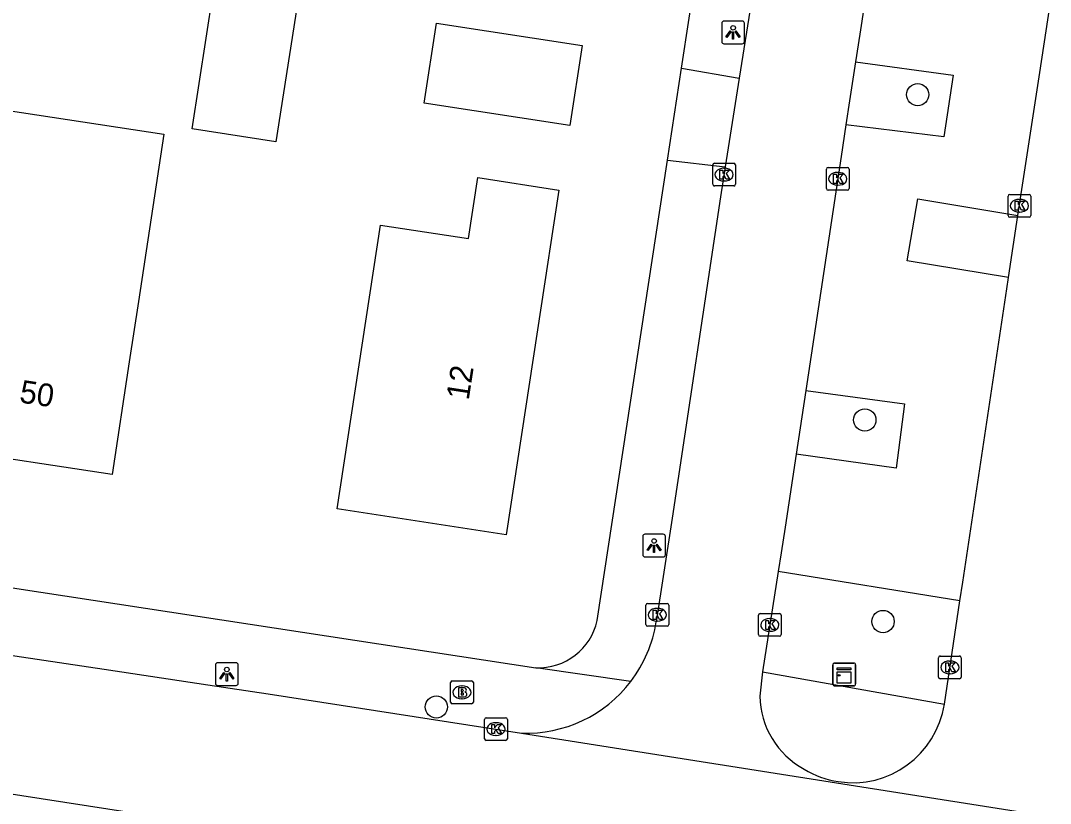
# Model space of a CAD drawing. Extents: x 161486 to 162249, y 379484 to 380829.
# Drawn here: x 161700.97 to 161746.18, y 380443.95 to 380478.3 of the extents above; entities that cross this region are included whole.
import ezdxf

# ---------------------------------------------------------------- set-up
doc = ezdxf.new("R2010")
doc.units = 0
for name, color, linetype in [('IMGEO_Boom', 7, 'Continuous'), ('IMGEO_Brandkraan', 7, 'Continuous'), ('IMGEO_Groenvoorziening', 7, 'Continuous'), ('IMGEO_Kast', 7, 'Continuous'), ('IMGEO_Kolk', 7, 'Continuous'), ('IMGEO_Lichtpunt', 7, 'Continuous'), ('IMGEO_Pand', 7, 'Continuous'), ('IMGEO_Pand_nummerreeks', 7, 'Continuous'), ('IMGEO_Rijbaan_lokaal_open', 7, 'Continuous'), ('IMGEO_Voetpad_open', 7, 'Continuous')]:
    doc.layers.add(name, color=color, linetype=linetype)

msp = doc.modelspace()

# ---------------------------------------------------------------- linework, layer by layer
at = {"layer": 'IMGEO_Boom'}
for centre in [(161740.352, 380475.05), (161738.03, 380460.775), (161738.832, 380451.929), (161719.223, 380448.179)]:
    msp.add_circle(centre, 0.489, dxfattribs=at)
at = {"layer": 'IMGEO_Brandkraan'}
for p, q in [((161719.844, 380448.396), (161719.844, 380449.248)), ((161719.919, 380449.322), (161720.771, 380449.322)), ((161720.332, 380449.102), (161720.357, 380449.102)), ((161720.845, 380449.248), (161720.845, 380448.396)), ((161720.355, 380448.542), (161720.33, 380448.542)), ((161720.771, 380448.322), (161719.919, 380448.322))]:
    msp.add_line(p, q, dxfattribs=at)
for points in [[(161719.844, 380448.396), (161719.844, 380449.248)], [(161719.919, 380449.322), (161720.771, 380449.322)], [(161720.192, 380449.022), (161720.192, 380448.622), (161720.405, 380448.622)], [(161720.423, 380449.022), (161720.192, 380449.022)], [(161720.845, 380449.248), (161720.845, 380448.396)], [(161720.371, 380448.941), (161720.317, 380448.941), (161720.317, 380448.865)], [(161720.317, 380448.865), (161720.37, 380448.865)], [(161720.379, 380448.789), (161720.317, 380448.789), (161720.317, 380448.708)], [(161720.317, 380448.708), (161720.379, 380448.708)], [(161720.771, 380448.322), (161719.919, 380448.322)]]:
    msp.add_lwpolyline(points, dxfattribs=at)
for centre, radius, start, end in [((161719.921, 380449.246), 0.0765, 91.552, 178.448), ((161719.921, 380449.246), 0.0765, 91.552, 178.448), ((161720.427, 380448.877), 0.145, 59.4692, 91.5367), ((161720.452, 380448.924), 0.0922, 285.5137, 58.1501), ((161720.769, 380449.246), 0.0765, 1.552, 88.448), ((161720.769, 380449.246), 0.0765, 1.552, 88.448), ((161720.372, 380448.903), 0.0379, 267.8285, 90.9355), ((161720.38, 380448.748), 0.0404, 269.8759, 90.5077), ((161720.411, 380448.873), 0.251, 268.6676, 293.5347), ((161720.457, 380448.732), 0.105, 301.3115, 78.989), ((161719.921, 380448.398), 0.0765, 181.552, 268.448), ((161719.921, 380448.398), 0.0765, 181.552, 268.448), ((161720.769, 380448.398), 0.0765, 271.552, 358.448), ((161720.769, 380448.398), 0.0765, 271.552, 358.448)]:
    msp.add_arc(centre, radius, start, end, dxfattribs=at)
for centre, major_axis, ratio, start_param, end_param in [((161720.331, 380448.822), (-0.387, 0.002), 0.722429, 4.712389, 7.853982), ((161720.356, 380448.822), (-0.39, 0.002), 0.717154, 1.570796, 4.712389)]:
    msp.add_ellipse(centre, major_axis=major_axis, ratio=ratio, start_param=start_param, end_param=end_param, dxfattribs=at)
at = {"layer": 'IMGEO_Groenvoorziening'}
for points in [[(161737.621, 380476.484), (161741.902, 380475.901), (161741.497, 380473.2), (161737.2, 380473.726)], [(161744.338, 380467.025), (161739.888, 380467.756), (161740.354, 380470.481), (161744.753, 380469.744)], [(161735.441, 380462.069), (161739.777, 380461.483), (161739.409, 380458.664), (161735.018, 380459.271)], [(161742.204, 380452.837), (161734.23, 380454.128)]]:
    msp.add_lwpolyline(points, dxfattribs=at)
at = {"layer": 'IMGEO_Kast'}
for p, q in [((161736.627, 380449.179), (161736.627, 380450.02)), ((161736.627, 380450.02), (161736.627, 380449.179)), ((161736.702, 380450.104), (161737.543, 380450.104)), ((161737.543, 380450.104), (161736.702, 380450.104)), ((161737.627, 380450.029), (161737.627, 380449.188)), ((161737.627, 380449.188), (161737.627, 380450.029)), ((161737.552, 380449.104), (161736.711, 380449.104)), ((161736.711, 380449.104), (161737.552, 380449.104))]:
    msp.add_line(p, q, dxfattribs=at)
for points in [[(161736.822, 380449.894), (161737.422, 380449.894), (161737.422, 380449.809), (161736.822, 380449.809), (161736.822, 380449.894)], [(161736.822, 380449.719), (161737.422, 380449.719), (161737.422, 380449.23), (161736.822, 380449.23), (161736.822, 380449.719)]]:
    msp.add_lwpolyline(points, dxfattribs=at)
msp.add_circle((161736.906, 380449.568), 0.0377, dxfattribs=at)
for centre, start, end in [((161736.705, 380450.026), 92.4484, 184.2845), ((161736.705, 380450.026), 92.4484, 184.2845), ((161737.549, 380450.026), 2.4484, 94.2845), ((161737.549, 380450.026), 2.4484, 94.2845), ((161736.705, 380449.182), 182.4484, 274.2845), ((161736.705, 380449.182), 182.4484, 274.2845), ((161737.549, 380449.182), 272.4484, 4.2845), ((161737.549, 380449.182), 272.4484, 4.2845)]:
    msp.add_arc(centre, 0.0779, start, end, dxfattribs=at)
at = {"layer": 'IMGEO_Kolk'}
for p, q in [((161731.427, 380472.041), (161732.279, 380472.041)), ((161731.352, 380471.115), (161731.352, 380471.967)), ((161731.84, 380471.821), (161731.865, 380471.821)), ((161732.353, 380471.967), (161732.353, 380471.115)), ((161736.342, 380470.93), (161736.342, 380471.782)), ((161736.417, 380471.856), (161737.269, 380471.856)), ((161736.83, 380471.636), (161736.855, 380471.636)), ((161737.343, 380471.782), (161737.343, 380470.93)), ((161731.863, 380471.261), (161731.838, 380471.261)), ((161732.279, 380471.041), (161731.427, 380471.041)), ((161737.269, 380470.856), (161736.417, 380470.856)), ((161736.853, 380471.076), (161736.828, 380471.076)), ((161744.392, 380470.673), (161745.244, 380470.673)), ((161744.317, 380469.747), (161744.317, 380470.599)), ((161744.805, 380470.453), (161744.83, 380470.453)), ((161745.318, 380470.599), (161745.318, 380469.747)), ((161744.828, 380469.893), (161744.803, 380469.893)), ((161745.244, 380469.673), (161744.392, 380469.673)), ((161728.42, 380451.799), (161728.42, 380452.651)), ((161728.495, 380452.725), (161729.347, 380452.725)), ((161729.421, 380452.651), (161729.421, 380451.799)), ((161728.908, 380452.505), (161728.933, 380452.505)), ((161733.36, 380451.354), (161733.36, 380452.206)), ((161733.435, 380452.28), (161734.287, 380452.28)), ((161734.361, 380452.206), (161734.361, 380451.354)), ((161729.347, 380451.725), (161728.495, 380451.725)), ((161728.931, 380451.945), (161728.906, 380451.945)), ((161733.848, 380452.06), (161733.873, 380452.06)), ((161734.287, 380451.28), (161733.435, 380451.28)), ((161733.871, 380451.5), (161733.846, 380451.5)), ((161741.264, 380449.49), (161741.264, 380450.342)), ((161741.339, 380450.416), (161742.191, 380450.416)), ((161742.265, 380450.342), (161742.265, 380449.49)), ((161741.752, 380450.196), (161741.777, 380450.196)), ((161741.775, 380449.636), (161741.75, 380449.636)), ((161742.191, 380449.416), (161741.339, 380449.416)), ((161721.337, 380446.783), (161721.337, 380447.635)), ((161721.412, 380447.709), (161722.264, 380447.709)), ((161722.338, 380447.635), (161722.338, 380446.783)), ((161721.825, 380447.489), (161721.85, 380447.489)), ((161721.848, 380446.929), (161721.823, 380446.929)), ((161722.264, 380446.709), (161721.412, 380446.709))]:
    msp.add_line(p, q, dxfattribs=at)
for points in [[(161731.427, 380472.041), (161732.279, 380472.041)], [(161731.352, 380471.115), (161731.352, 380471.967)], [(161731.673, 380471.741), (161731.796, 380471.741), (161731.796, 380471.59), (161731.926, 380471.741), (161732.09, 380471.741), (161731.944, 380471.59), (161732.097, 380471.341), (161731.945, 380471.341), (161731.86, 380471.505), (161731.796, 380471.438), (161731.796, 380471.341), (161731.673, 380471.341), (161731.673, 380471.741)], [(161732.353, 380471.967), (161732.353, 380471.115)], [(161736.342, 380470.93), (161736.342, 380471.782)], [(161736.417, 380471.856), (161737.269, 380471.856)], [(161737.343, 380471.782), (161737.343, 380470.93)], [(161736.663, 380471.556), (161736.786, 380471.556), (161736.786, 380471.405), (161736.916, 380471.556), (161737.08, 380471.556), (161736.934, 380471.405), (161737.087, 380471.156), (161736.935, 380471.156), (161736.85, 380471.32), (161736.786, 380471.253), (161736.786, 380471.156), (161736.663, 380471.156), (161736.663, 380471.556)], [(161732.279, 380471.041), (161731.427, 380471.041)], [(161737.269, 380470.856), (161736.417, 380470.856)], [(161744.392, 380470.673), (161745.244, 380470.673)], [(161744.317, 380469.747), (161744.317, 380470.599)], [(161744.638, 380470.373), (161744.761, 380470.373), (161744.761, 380470.222), (161744.891, 380470.373), (161745.055, 380470.373), (161744.909, 380470.222), (161745.062, 380469.973), (161744.91, 380469.973), (161744.825, 380470.137), (161744.761, 380470.07), (161744.761, 380469.973), (161744.638, 380469.973), (161744.638, 380470.373)], [(161745.318, 380470.599), (161745.318, 380469.747)], [(161745.244, 380469.673), (161744.392, 380469.673)], [(161728.42, 380451.799), (161728.42, 380452.651)], [(161728.495, 380452.725), (161729.347, 380452.725)], [(161729.421, 380452.651), (161729.421, 380451.799)], [(161728.741, 380452.425), (161728.864, 380452.425), (161728.864, 380452.274), (161728.994, 380452.425), (161729.158, 380452.425), (161729.012, 380452.274), (161729.165, 380452.025), (161729.013, 380452.025), (161728.928, 380452.189), (161728.864, 380452.122), (161728.864, 380452.025), (161728.741, 380452.025), (161728.741, 380452.425)], [(161733.36, 380451.354), (161733.36, 380452.206)], [(161733.435, 380452.28), (161734.287, 380452.28)], [(161734.361, 380452.206), (161734.361, 380451.354)], [(161729.347, 380451.725), (161728.495, 380451.725)], [(161733.681, 380451.98), (161733.804, 380451.98), (161733.804, 380451.829), (161733.934, 380451.98), (161734.098, 380451.98), (161733.952, 380451.829), (161734.105, 380451.58), (161733.953, 380451.58), (161733.868, 380451.744), (161733.804, 380451.677), (161733.804, 380451.58), (161733.681, 380451.58), (161733.681, 380451.98)], [(161734.287, 380451.28), (161733.435, 380451.28)], [(161741.264, 380449.49), (161741.264, 380450.342)], [(161741.339, 380450.416), (161742.191, 380450.416)], [(161742.265, 380450.342), (161742.265, 380449.49)], [(161741.585, 380450.116), (161741.708, 380450.116), (161741.708, 380449.965), (161741.838, 380450.116), (161742.002, 380450.116), (161741.856, 380449.965), (161742.009, 380449.716), (161741.857, 380449.716), (161741.772, 380449.88), (161741.708, 380449.813), (161741.708, 380449.716), (161741.585, 380449.716), (161741.585, 380450.116)], [(161742.191, 380449.416), (161741.339, 380449.416)], [(161721.337, 380446.783), (161721.337, 380447.635)], [(161721.412, 380447.709), (161722.264, 380447.709)], [(161722.338, 380447.635), (161722.338, 380446.783)], [(161721.658, 380447.409), (161721.781, 380447.409), (161721.781, 380447.258), (161721.911, 380447.409), (161722.075, 380447.409), (161721.929, 380447.258), (161722.082, 380447.009), (161721.93, 380447.009), (161721.845, 380447.173), (161721.781, 380447.106), (161721.781, 380447.009), (161721.658, 380447.009), (161721.658, 380447.409)], [(161722.264, 380446.709), (161721.412, 380446.709)]]:
    msp.add_lwpolyline(points, dxfattribs=at)
for centre, start, end in [((161731.429, 380471.965), 91.552, 178.448), ((161731.429, 380471.965), 91.552, 178.448), ((161732.277, 380471.965), 1.552, 88.448), ((161732.277, 380471.965), 1.552, 88.448), ((161736.419, 380471.78), 91.552, 178.448), ((161736.419, 380471.78), 91.552, 178.448), ((161737.267, 380471.78), 1.552, 88.448), ((161737.267, 380471.78), 1.552, 88.448), ((161731.429, 380471.117), 181.552, 268.448), ((161731.429, 380471.117), 181.552, 268.448), ((161732.277, 380471.117), 271.552, 358.448), ((161732.277, 380471.117), 271.552, 358.448), ((161736.419, 380470.932), 181.552, 268.448), ((161736.419, 380470.932), 181.552, 268.448), ((161737.267, 380470.932), 271.552, 358.448), ((161737.267, 380470.932), 271.552, 358.448), ((161744.394, 380470.597), 91.552, 178.448), ((161744.394, 380470.597), 91.552, 178.448), ((161745.242, 380470.597), 1.552, 88.448), ((161745.242, 380470.597), 1.552, 88.448), ((161744.394, 380469.749), 181.552, 268.448), ((161744.394, 380469.749), 181.552, 268.448), ((161745.242, 380469.749), 271.552, 358.448), ((161745.242, 380469.749), 271.552, 358.448), ((161728.497, 380452.649), 91.552, 178.448), ((161728.497, 380452.649), 91.552, 178.448), ((161729.345, 380452.649), 1.552, 88.448), ((161729.345, 380452.649), 1.552, 88.448), ((161733.437, 380452.204), 91.552, 178.448), ((161733.437, 380452.204), 91.552, 178.448), ((161734.285, 380452.204), 1.552, 88.448), ((161734.285, 380452.204), 1.552, 88.448), ((161728.497, 380451.801), 181.552, 268.448), ((161728.497, 380451.801), 181.552, 268.448), ((161729.345, 380451.801), 271.552, 358.448), ((161729.345, 380451.801), 271.552, 358.448), ((161733.437, 380451.356), 181.552, 268.448), ((161733.437, 380451.356), 181.552, 268.448), ((161734.285, 380451.356), 271.552, 358.448), ((161734.285, 380451.356), 271.552, 358.448), ((161741.341, 380450.34), 91.552, 178.448), ((161741.341, 380450.34), 91.552, 178.448), ((161742.189, 380450.34), 1.552, 88.448), ((161742.189, 380450.34), 1.552, 88.448), ((161741.341, 380449.492), 181.552, 268.448), ((161741.341, 380449.492), 181.552, 268.448), ((161742.189, 380449.492), 271.552, 358.448), ((161742.189, 380449.492), 271.552, 358.448), ((161721.414, 380447.633), 91.552, 178.448), ((161721.414, 380447.633), 91.552, 178.448), ((161722.262, 380447.633), 1.552, 88.448), ((161722.262, 380447.633), 1.552, 88.448), ((161721.414, 380446.785), 181.552, 268.448), ((161721.414, 380446.785), 181.552, 268.448), ((161722.262, 380446.785), 271.552, 358.448), ((161722.262, 380446.785), 271.552, 358.448)]:
    msp.add_arc(centre, 0.0765, start, end, dxfattribs=at)
for centre, major_axis, ratio, start_param, end_param in [((161731.839, 380471.541), (-0.387, 0.002), 0.722429, 4.712389, 7.853982), ((161731.864, 380471.541), (-0.39, 0.002), 0.717154, 1.570796, 4.712389), ((161736.829, 380471.356), (-0.387, 0.002), 0.722429, 4.712389, 7.853982), ((161736.854, 380471.356), (-0.39, 0.002), 0.717154, 1.570796, 4.712389), ((161744.804, 380470.173), (-0.387, 0.002), 0.722429, 4.712389, 7.853982), ((161744.829, 380470.173), (-0.39, 0.002), 0.717154, 1.570796, 4.712389), ((161728.907, 380452.225), (-0.387, 0.002), 0.722429, 4.712389, 7.853982), ((161728.932, 380452.225), (-0.39, 0.002), 0.717154, 1.570796, 4.712389), ((161733.847, 380451.78), (-0.387, 0.002), 0.722429, 4.712389, 7.853982), ((161733.872, 380451.78), (-0.39, 0.002), 0.717154, 1.570796, 4.712389), ((161741.751, 380449.916), (-0.387, 0.002), 0.722429, 4.712389, 7.853982), ((161741.776, 380449.916), (-0.39, 0.002), 0.717154, 1.570796, 4.712389), ((161721.824, 380447.209), (-0.387, 0.002), 0.722429, 4.712389, 7.853982), ((161721.849, 380447.209), (-0.39, 0.002), 0.717154, 1.570796, 4.712389)]:
    msp.add_ellipse(centre, major_axis=major_axis, ratio=ratio, start_param=start_param, end_param=end_param, dxfattribs=at)
at = {"layer": 'IMGEO_Lichtpunt'}
for p, q in [((161731.749, 380478.184), (161731.749, 380477.377)), ((161731.749, 380478.184), (161731.749, 380477.377)), ((161732.651, 380478.279), (161731.843, 380478.279)), ((161732.651, 380478.279), (161731.843, 380478.279)), ((161732.745, 380477.377), (161732.745, 380478.184)), ((161732.745, 380477.377), (161732.745, 380478.184)), ((161731.843, 380477.283), (161732.651, 380477.283)), ((161731.843, 380477.283), (161732.651, 380477.283)), ((161729.184, 380455.76), (161728.376, 380455.76)), ((161729.184, 380455.76), (161728.376, 380455.76)), ((161728.282, 380455.665), (161728.282, 380454.858)), ((161728.282, 380455.665), (161728.282, 380454.858)), ((161729.278, 380454.858), (161729.278, 380455.665)), ((161729.278, 380454.858), (161729.278, 380455.665)), ((161728.376, 380454.764), (161729.184, 380454.764)), ((161728.376, 380454.764), (161729.184, 380454.764)), ((161709.525, 380450.024), (161709.525, 380449.217)), ((161709.525, 380450.024), (161709.525, 380449.217)), ((161710.427, 380450.119), (161709.619, 380450.119)), ((161710.427, 380450.119), (161709.619, 380450.119)), ((161710.521, 380449.217), (161710.521, 380450.024)), ((161710.521, 380449.217), (161710.521, 380450.024)), ((161709.619, 380449.123), (161710.427, 380449.123)), ((161709.619, 380449.123), (161710.427, 380449.123))]:
    msp.add_line(p, q, dxfattribs=at)
for points in [[(161732.123, 380477.848), (161732.162, 380477.82), (161731.974, 380477.558), (161731.936, 380477.585), (161732.123, 380477.848)], [(161732.225, 380477.8), (161732.272, 380477.8), (161732.272, 380477.478), (161732.225, 380477.478), (161732.225, 380477.8)], [(161732.335, 380477.82), (161732.373, 380477.847), (161732.56, 380477.585), (161732.521, 380477.557), (161732.335, 380477.82)], [(161728.656, 380455.329), (161728.695, 380455.301), (161728.507, 380455.039), (161728.469, 380455.066), (161728.656, 380455.329)], [(161728.868, 380455.301), (161728.906, 380455.328), (161729.093, 380455.066), (161729.054, 380455.038), (161728.868, 380455.301)], [(161728.758, 380455.281), (161728.805, 380455.281), (161728.805, 380454.959), (161728.758, 380454.959), (161728.758, 380455.281)], [(161709.899, 380449.688), (161709.938, 380449.66), (161709.75, 380449.398), (161709.712, 380449.425), (161709.899, 380449.688)], [(161710.001, 380449.64), (161710.048, 380449.64), (161710.048, 380449.318), (161710.001, 380449.318), (161710.001, 380449.64)], [(161710.111, 380449.66), (161710.149, 380449.687), (161710.336, 380449.425), (161710.297, 380449.397), (161710.111, 380449.66)]]:
    msp.add_lwpolyline(points, dxfattribs=at)
for centre in [(161732.248, 380477.982), (161728.781, 380455.463), (161710.024, 380449.822)]:
    msp.add_circle(centre, 0.0994, dxfattribs=at)
for centre, start, end in [((161731.843, 380478.184), 90, 180), ((161731.843, 380478.184), 90, 180), ((161732.651, 380478.184), 0, 90), ((161732.651, 380478.184), 0, 90), ((161731.843, 380477.377), 180, 270), ((161731.843, 380477.377), 180, 270), ((161732.651, 380477.377), 270, 0), ((161732.651, 380477.377), 270, 360), ((161728.376, 380455.665), 90, 180), ((161728.376, 380455.665), 90, 180), ((161729.184, 380455.665), 0, 90), ((161729.184, 380455.665), 0, 90), ((161728.376, 380454.858), 180, 270), ((161728.376, 380454.858), 180, 270), ((161729.184, 380454.858), 270, 0), ((161729.184, 380454.858), 270, 360), ((161709.619, 380450.024), 90, 180), ((161709.619, 380450.024), 90, 180), ((161710.427, 380450.024), 0, 90), ((161710.427, 380450.024), 0, 90), ((161709.619, 380449.217), 180, 270), ((161709.619, 380449.217), 180, 270), ((161710.427, 380449.217), 270, 0), ((161710.427, 380449.217), 270, 360)]:
    msp.add_arc(centre, 0.0946, start, end, dxfattribs=at)
at = {"layer": 'IMGEO_Pand'}
for points in [[(161709.429, 380479.53), (161713.108, 380478.958), (161712.179, 380472.983), (161708.5, 380473.555), (161709.429, 380479.53)], [(161725.618, 380477.213), (161725.082, 380473.697), (161718.686, 380474.672), (161719.223, 380478.188), (161725.618, 380477.213)], [(161707.26, 380473.313), (161706.142, 380465.969), (161705.738, 380463.319), (161704.985, 380458.376), (161697.651, 380459.493), (161699.139, 380469.262), (161696.658, 380469.64), (161697.411, 380474.583), (161697.445, 380474.807), (161707.26, 380473.313)], [(161721.043, 380471.408), (161724.601, 380470.865), (161724.192, 380468.187), (161724.147, 380467.895), (161722.293, 380455.739), (161714.867, 380456.872), (161716.766, 380469.32), (161720.634, 380468.73), (161721.043, 380471.408)]]:
    msp.add_lwpolyline(points, dxfattribs=at)
at = {"layer": 'IMGEO_Rijbaan_lokaal_open'}
for points in [[(161744.753, 380469.744), (161744.957, 380471.08), (161745.711, 380476.014), (161746.655, 380482.196), (161749.364, 380500), (161749.564, 380501.311), (161750.302, 380506.085)], [(161741.342, 380500.764), (161741.225, 380500), (161737.808, 380477.707), (161737.621, 380476.484)], [(161734.457, 380488.318), (161733.623, 380482.759), (161732.522, 380475.779)], [(161737.621, 380476.484), (161737.36, 380474.784), (161737.2, 380473.726)], [(161732.522, 380475.779), (161731.907, 380471.88)], [(161737.2, 380473.726), (161736.99, 380472.333), (161735.441, 380462.069)], [(161731.907, 380471.88), (161731.699, 380470.562), (161729.579, 380456.467), (161728.874, 380451.915)], [(161744.338, 380467.025), (161744.753, 380469.744)], [(161742.204, 380452.837), (161742.327, 380453.656), (161744.263, 380466.534), (161744.338, 380467.025)], [(161735.441, 380462.069), (161735.018, 380459.271)], [(161735.018, 380459.271), (161734.535, 380456.068), (161734.359, 380454.949), (161734.23, 380454.128)], [(161660.774, 380456.435), (161669.297, 380455.18), (161681.29, 380453.395), (161687.434, 380452.451), (161691.961, 380451.756), (161697.076, 380450.97), (161704.644, 380449.834), (161709.188, 380449.153), (161711.844, 380448.754), (161722.958, 380447.035)], [(161734.23, 380454.128), (161733.536, 380449.72)], [(161741.522, 380448.297), (161742.204, 380452.837)], [(161733.536, 380449.72), (161733.427, 380448.661)], [(161722.958, 380447.035), (161750.621, 380442.671)], [(161810.928, 380426.326), (161804.301, 380427.547), (161792.014, 380429.675), (161784.503, 380430.965), (161777.227, 380432.215), (161777.074, 380432.24), (161763.28, 380434.453), (161754.881, 380435.751), (161744.785, 380437.458), (161740.249, 380438.226), (161736.799, 380438.809), (161729.763, 380439.91), (161729.261, 380439.989), (161725.346, 380440.572), (161718.187, 380441.637), (161707.293, 380443.311), (161705.835, 380443.535), (161699.969, 380444.448), (161691.17, 380445.817)]]:
    msp.add_lwpolyline(points, dxfattribs=at)
for centre, radius, start, end in [((161723.16, 380452.811), 5.784, 322.6535, 351.0923), ((161723.171, 380452.8), 5.769, 267.889, 322.673), ((161737.106, 380448.697), 3.68, 180.5617, 241.8427), ((161737.495, 380448.931), 4.077, 261.07, 351.0476), ((161737.496, 380448.928), 4.074, 238.5466, 261.0499)]:
    msp.add_arc(centre, radius, start, end, dxfattribs=at)
at = {"layer": 'IMGEO_Voetpad_open'}
for points in [[(161729.989, 380476.206), (161732.005, 380489.393)], [(161729.373, 380472.172), (161729.989, 380476.206)], [(161729.989, 380476.206), (161732.522, 380475.779)], [(161726.286, 380451.976), (161729.373, 380472.172)], [(161729.373, 380472.172), (161731.907, 380471.88)], [(161657.919, 380460.405), (161659.307, 380459.731), (161660.495, 380459.537), (161723.59, 380449.899)], [(161727.758, 380449.302), (161723.59, 380449.899)], [(161733.536, 380449.72), (161741.522, 380448.297)]]:
    msp.add_lwpolyline(points, dxfattribs=at)
msp.add_arc((161723.687, 380452.561), 2.664, 267.9139, 347.3075, dxfattribs=at)

# ---------------------------------------------------------------- texts
at = {"layer": 'IMGEO_Pand_nummerreeks'}
for s, rotation, p in [('12', 81.3261, (161720.64, 380461.613)), ('50', 351.3402, (161700.884, 380461.549))]:
    msp.add_text(s, height=1, rotation=rotation, dxfattribs=at).set_placement(p)

doc.saveas('drawing.dxf')
